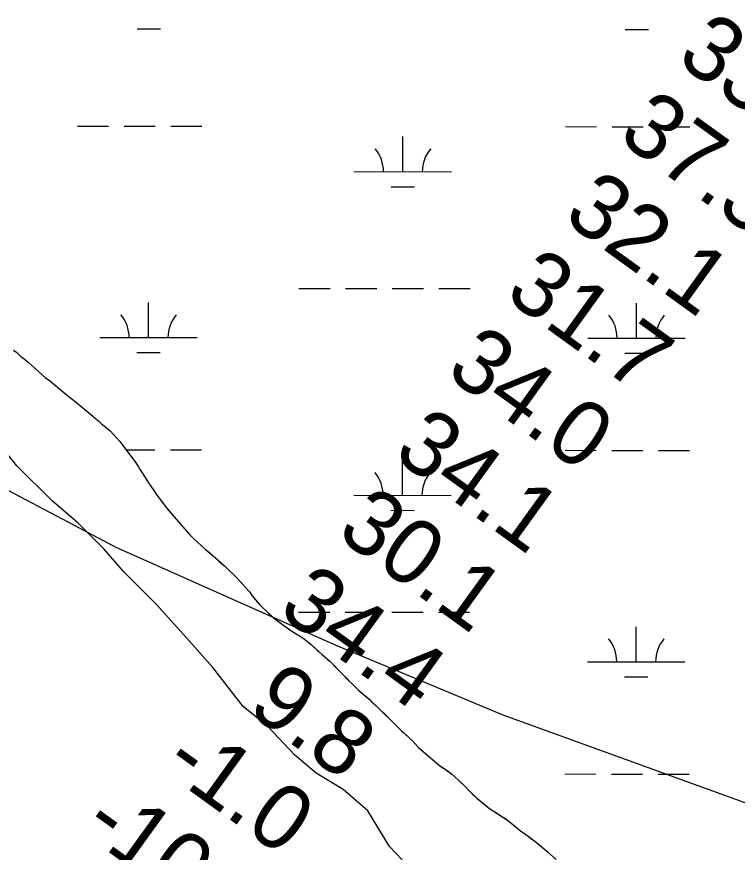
# Model space of a CAD drawing. Extents: x 3148686 to 3186545, y 916144 to 941516.
# Drawn here: x 3160862 to 3161603, y 938344 to 939203 of the extents above; entities that cross this region are included whole.
import ezdxf

# ---------------------------------------------------------------- set-up
doc = ezdxf.new("R2010")
doc.units = 0
for name, color, linetype in [('V-RIVR-EDGE', 7, 'Continuous'), ('V-RIVR-RANG', 7, 'Continuous'), ('V-SITE-VEGE', 7, 'Continuous'), ('V-TOPO-BNDY', 7, 'Continuous'), ('V-WETL-SWMP', 7, 'Continuous')]:
    doc.layers.add(name, color=color, linetype=linetype)

msp = doc.modelspace()

# ---------------------------------------------------------------- linework, layer by layer
at = {"layer": 'V-RIVR-EDGE'}
msp.add_lwpolyline([(3161258.64, 938336.18), (3161245.71, 938349.7), (3161223.5, 938386.58), (3161198.14, 938408.42), (3161170.18, 938425.09), (3161148.44, 938443.81), (3161119.99, 938473.96), (3161095.15, 938493.73), (3161064.13, 938533.74), (3161036.72, 938564.41), (3161005.69, 938598.71), (3160972.58, 938631.99), (3160951.89, 938655.89), (3160924.99, 938682.41), (3160899.11, 938704.77), (3160862.38, 938741.17), (3160806.54, 938811.32)], dxfattribs=at)
at = {"layer": 'V-SITE-VEGE'}
for p, q in [((3160862.24, 938857.39), (3160866.63, 938853.48)), ((3160866.63, 938853.48), (3160870.04, 938851)), ((3160870.04, 938851), (3160874.44, 938847.29)), ((3160874.44, 938847.29), (3160877.43, 938844.41)), ((3160877.43, 938844.41), (3160892.02, 938831.65)), ((3160892.02, 938831.65), (3160895.63, 938828.96)), ((3160895.63, 938828.96), (3160913.03, 938814.53)), ((3160913.03, 938814.53), (3160922.43, 938807.31)), ((3160922.43, 938807.31), (3160934.03, 938797.42)), ((3160934.03, 938797.42), (3160943.04, 938790.2)), ((3160943.04, 938790.2), (3160946.44, 938787.32)), ((3160946.44, 938787.32), (3160949.63, 938784.23)), ((3160949.63, 938784.23), (3160953.83, 938780.93)), ((3160953.83, 938780.93), (3160958.23, 938777.02)), ((3160958.23, 938777.02), (3160961.82, 938773.32)), ((3160961.82, 938773.32), (3160968.19, 938766.15)), ((3160968.19, 938766.15), (3160984.07, 938745.06)), ((3160984.07, 938745.06), (3160987.44, 938740.15)), ((3160987.44, 938740.15), (3160989.22, 938736.89)), ((3160989.22, 938736.89), (3160991.2, 938734.02)), ((3160991.2, 938734.02), (3160998.32, 938722.58)), ((3160998.32, 938722.58), (3161002.69, 938716.64)), ((3161002.69, 938716.64), (3161006.65, 938710.72)), ((3161006.65, 938710.72), (3161016.38, 938697.82)), ((3161016.38, 938697.82), (3161021.75, 938691.26)), ((3161021.75, 938691.26), (3161028.72, 938683.46)), ((3161028.72, 938683.46), (3161032.69, 938678.55)), ((3161032.69, 938678.55), (3161040.26, 938670.14)), ((3161040.26, 938670.14), (3161044.26, 938666.43)), ((3161044.26, 938666.43), (3161047.45, 938663.15)), ((3161047.45, 938663.15), (3161053.04, 938658.21)), ((3161053.04, 938658.21), (3161056.09, 938655.52)), ((3161056.09, 938655.52), (3161064.25, 938648.47)), ((3161064.25, 938648.47), (3161075.96, 938638.13)), ((3161075.96, 938638.13), (3161088.72, 938625.99)), ((3161088.72, 938625.99), (3161092.1, 938622.31)), ((3161092.1, 938622.31), (3161098.23, 938615.35)), ((3161098.23, 938615.35), (3161101.53, 938611.42)), ((3161101.53, 938611.42), (3161104.6, 938607.49)), ((3161104.6, 938607.49), (3161110.24, 938600.62)), ((3161110.24, 938600.62), (3161112.41, 938598.08)), ((3161112.41, 938598.08), (3161115.4, 938595.04)), ((3161115.4, 938595.04), (3161118.38, 938592.26)), ((3161118.38, 938592.26), (3161126.54, 938584.95)), ((3161126.54, 938584.95), (3161129.21, 938582.74)), ((3161129.21, 938582.74), (3161135.52, 938577.97)), ((3161135.52, 938577.97), (3161144.34, 938571.89)), ((3161144.34, 938571.89), (3161150.65, 938567.85)), ((3161150.65, 938567.85), (3161153.89, 938565.96)), ((3161153.89, 938565.96), (3161157.04, 938563.82)), ((3161157.04, 938563.82), (3161161.49, 938560.53)), ((3161161.49, 938560.53), (3161165.37, 938557.16)), ((3161165.37, 938557.16), (3161173.28, 938549.78)), ((3161173.28, 938549.78), (3161176.59, 938546.99)), ((3161176.59, 938546.99), (3161184.27, 938540.1)), ((3161184.27, 938540.1), (3161186.69, 938537.81)), ((3161186.69, 938537.81), (3161195.32, 938529.04)), ((3161195.32, 938529.04), (3161203.79, 938520.11)), ((3161203.79, 938520.11), (3161206.78, 938517.4)), ((3161206.78, 938517.4), (3161213.96, 938510.51)), ((3161213.96, 938510.51), (3161216.47, 938508.22)), ((3161216.47, 938508.22), (3161224.63, 938501.16)), ((3161224.63, 938501.16), (3161236.5, 938490)), ((3161236.5, 938490), (3161245.14, 938481.56)), ((3161245.14, 938481.56), (3161252.24, 938474.35)), ((3161252.24, 938474.35), (3161257.81, 938469.02)), ((3161257.81, 938469.02), (3161269.35, 938458.28)), ((3161269.35, 938458.28), (3161275.97, 938451.23)), ((3161275.97, 938451.23), (3161297.13, 938432.93)), ((3161297.13, 938432.93), (3161303.04, 938429.14)), ((3161303.04, 938429.14), (3161309.67, 938424.29)), ((3161309.67, 938424.29), (3161313.23, 938421.18)), ((3161313.23, 938421.18), (3161316.46, 938418.14)), ((3161316.46, 938418.14), (3161322.75, 938411.99)), ((3161322.75, 938411.99), (3161327.52, 938407.16)), ((3161327.52, 938407.16), (3161335.43, 938399.53)), ((3161335.43, 938399.53), (3161341.24, 938394.77)), ((3161341.24, 938394.77), (3161347.31, 938390.01)), ((3161347.31, 938390.01), (3161350.62, 938387.62)), ((3161350.62, 938387.62), (3161353.94, 938385.4)), ((3161353.94, 938385.4), (3161363.09, 938379.64)), ((3161363.09, 938379.64), (3161368.83, 938375.36)), ((3161368.83, 938375.36), (3161380.39, 938366)), ((3161380.39, 938366), (3161385.8, 938361.98)), ((3161385.8, 938361.98), (3161388.31, 938360.25)), ((3161388.31, 938360.25), (3161396.8, 938353.92)), ((3161396.8, 938353.92), (3161405.21, 938347.11)), ((3161405.21, 938347.11), (3161417.24, 938336.52))]:
    msp.add_line(p, q, dxfattribs=at)
at = {"layer": 'V-TOPO-BNDY'}
msp.add_lwpolyline([(3163062.31, 937127.32), (3163042.08, 937333.1), (3163017.03, 937479.87), (3162982.49, 937628.74), (3162942.16, 937741.6), (3162886.84, 937839.58), (3162771.84, 937963.73), (3162694.07, 938030.53), (3162300.86, 938206.75), (3162175.04, 938243.09), (3161984.61, 938304.69), (3161799.5, 938349.13), (3161614.4, 938393.58), (3161488.55, 938439.11), (3161362.7, 938484.64), (3161190.8, 938556.46), (3160964.51, 938657), (3160729.71, 938780.63), (3160591.89, 938870.33), (3160455.53, 938975.16), (3160435.15, 938990.83), (3160220.3, 939197.87)], dxfattribs=at)
at = {"layer": 'V-WETL-SWMP'}
for p, q in [((3160986.18, 939190.12), (3161010.18, 939190.1)), ((3161488.09, 939189.59), (3161512.09, 939189.57)), ((3160924.67, 939090.19), (3160956.67, 939090.15)), ((3160972.67, 939090.14), (3161004.67, 939090.1)), ((3161020.67, 939090.08), (3161052.67, 939090.05)), ((3161426.58, 939089.66), (3161458.58, 939089.62)), ((3161474.58, 939089.61), (3161506.58, 939089.57)), ((3161522.58, 939089.56), (3161554.58, 939089.52)), ((3161259.47, 939043.4), (3161259.5, 939079.4)), ((3161209.47, 939043.46), (3161309.47, 939043.35)), ((3161247.45, 939027.98), (3161271.45, 939027.96)), ((3161152.5, 938923.44), (3161184.5, 938923.41)), ((3161200.5, 938923.39), (3161232.5, 938923.36)), ((3161248.5, 938923.34), (3161280.5, 938923.31)), ((3161296.5, 938923.29), (3161328.5, 938923.26)), ((3160997.85, 938872.87), (3160997.89, 938908.87)), ((3161499.76, 938872.34), (3161499.8, 938908.34)), ((3160947.85, 938872.92), (3161047.85, 938872.81)), ((3161449.76, 938872.39), (3161549.76, 938872.28)), ((3160859.03, 938859.87), (3160862.24, 938857.39)), ((3160859.03, 938859.87), (3160862.24, 938857.39)), ((3160862.24, 938857.39), (3160866.63, 938853.48)), ((3160862.24, 938857.39), (3160866.63, 938853.48)), ((3160866.63, 938853.48), (3160870.04, 938851)), ((3160866.63, 938853.48), (3160870.04, 938851)), ((3160870.04, 938851), (3160874.44, 938847.29)), ((3160870.04, 938851), (3160874.44, 938847.29)), ((3160985.83, 938857.45), (3161009.83, 938857.42)), ((3161487.74, 938856.92), (3161511.74, 938856.89)), ((3160874.44, 938847.29), (3160877.43, 938844.41)), ((3160874.44, 938847.29), (3160877.43, 938844.41)), ((3160877.43, 938844.41), (3160892.02, 938831.65)), ((3160877.43, 938844.41), (3160892.02, 938831.65)), ((3160892.02, 938831.65), (3160895.63, 938828.96)), ((3160892.02, 938831.65), (3160895.63, 938828.96)), ((3160895.63, 938828.96), (3160913.03, 938814.53)), ((3160895.63, 938828.96), (3160913.03, 938814.53)), ((3160913.03, 938814.53), (3160922.44, 938807.31)), ((3160913.03, 938814.53), (3160922.44, 938807.31)), ((3160922.44, 938807.31), (3160934.03, 938797.42)), ((3160922.44, 938807.31), (3160934.03, 938797.42)), ((3160934.03, 938797.42), (3160943.04, 938790.2)), ((3160934.03, 938797.42), (3160943.04, 938790.2)), ((3160943.04, 938790.2), (3160946.44, 938787.32)), ((3160943.04, 938790.2), (3160946.44, 938787.32)), ((3160946.44, 938787.32), (3160949.63, 938784.24)), ((3160946.44, 938787.32), (3160949.63, 938784.24)), ((3160949.63, 938784.24), (3160953.83, 938780.93)), ((3160949.63, 938784.24), (3160953.83, 938780.93)), ((3160953.83, 938780.93), (3160958.23, 938777.02)), ((3160953.83, 938780.93), (3160958.23, 938777.02)), ((3160958.23, 938777.02), (3160961.82, 938773.33)), ((3160958.23, 938777.02), (3160961.82, 938773.33)), ((3160961.82, 938773.33), (3160968.19, 938766.15)), ((3160961.82, 938773.33), (3160968.19, 938766.15)), ((3160968.19, 938766.15), (3160984.08, 938745.06)), ((3160968.19, 938766.15), (3160984.08, 938745.06)), ((3160974.74, 938757.46), (3161004.32, 938757.43)), ((3161020.32, 938757.41), (3161052.32, 938757.38)), ((3161426.23, 938756.98), (3161458.23, 938756.95)), ((3161474.23, 938756.93), (3161506.23, 938756.9)), ((3161522.23, 938756.88), (3161554.23, 938756.85)), ((3161259.12, 938710.73), (3161259.15, 938746.73)), ((3160984.08, 938745.06), (3160987.44, 938740.15)), ((3160984.08, 938745.06), (3160987.44, 938740.15)), ((3160987.44, 938740.15), (3160989.22, 938736.89)), ((3160987.44, 938740.15), (3160989.22, 938736.89)), ((3160989.22, 938736.89), (3160991.2, 938734.02)), ((3160989.22, 938736.89), (3160991.2, 938734.02)), ((3160991.2, 938734.02), (3160998.32, 938722.58)), ((3160991.2, 938734.02), (3160998.32, 938722.58)), ((3160998.32, 938722.58), (3161002.69, 938716.65)), ((3160998.32, 938722.58), (3161002.69, 938716.65)), ((3161002.69, 938716.65), (3161006.65, 938710.72)), ((3161002.69, 938716.65), (3161006.65, 938710.72)), ((3161006.65, 938710.72), (3161016.38, 938697.82)), ((3161006.65, 938710.72), (3161016.38, 938697.82)), ((3161209.12, 938710.78), (3161309.12, 938710.68)), ((3161016.38, 938697.82), (3161021.75, 938691.26)), ((3161016.38, 938697.82), (3161021.75, 938691.26)), ((3161247.1, 938695.31), (3161271.1, 938695.28)), ((3161021.75, 938691.26), (3161028.72, 938683.47)), ((3161021.75, 938691.26), (3161028.72, 938683.47)), ((3161028.72, 938683.47), (3161032.69, 938678.55)), ((3161028.72, 938683.47), (3161032.69, 938678.55)), ((3161032.69, 938678.55), (3161040.26, 938670.14)), ((3161032.69, 938678.55), (3161040.26, 938670.14)), ((3161040.26, 938670.14), (3161044.26, 938666.43)), ((3161040.26, 938670.14), (3161044.26, 938666.43)), ((3161044.26, 938666.43), (3161047.45, 938663.15)), ((3161044.26, 938666.43), (3161047.45, 938663.15)), ((3161047.45, 938663.15), (3161053.04, 938658.21)), ((3161047.45, 938663.15), (3161053.04, 938658.21)), ((3161053.04, 938658.21), (3161056.09, 938655.53)), ((3161053.04, 938658.21), (3161056.09, 938655.53)), ((3161056.09, 938655.53), (3161059.24, 938652.82)), ((3161056.09, 938655.53), (3161059.24, 938652.82)), ((3161059.24, 938652.82), (3161061.58, 938650.77)), ((3161059.24, 938652.82), (3161061.58, 938650.77)), ((3161061.58, 938650.77), (3161064.25, 938648.47)), ((3161061.58, 938650.77), (3161064.25, 938648.47)), ((3161064.25, 938648.47), (3161066.75, 938646.25)), ((3161064.25, 938648.47), (3161066.75, 938646.25)), ((3161066.75, 938646.25), (3161070.31, 938643.13)), ((3161066.75, 938646.25), (3161070.31, 938643.13)), ((3161070.31, 938643.13), (3161073.05, 938640.67)), ((3161070.31, 938643.13), (3161073.05, 938640.67)), ((3161073.05, 938640.67), (3161075.96, 938638.13)), ((3161073.05, 938640.67), (3161075.96, 938638.13)), ((3161075.96, 938638.13), (3161078.22, 938636)), ((3161075.96, 938638.13), (3161078.22, 938636)), ((3161078.22, 938636), (3161081.29, 938633.13)), ((3161078.22, 938636), (3161081.29, 938633.13)), ((3161081.29, 938633.13), (3161084.04, 938630.42)), ((3161081.29, 938633.13), (3161084.04, 938630.42)), ((3161084.04, 938630.42), (3161086.3, 938628.29)), ((3161084.04, 938630.42), (3161086.3, 938628.29)), ((3161086.3, 938628.29), (3161088.72, 938625.99)), ((3161086.3, 938628.29), (3161088.72, 938625.99)), ((3161088.72, 938625.99), (3161092.11, 938622.31)), ((3161088.72, 938625.99), (3161092.11, 938622.31)), ((3161092.11, 938622.31), (3161094.93, 938619.11)), ((3161092.11, 938622.31), (3161094.93, 938619.11)), ((3161094.93, 938619.11), (3161098.23, 938615.35)), ((3161094.93, 938619.11), (3161098.23, 938615.35)), ((3161098.23, 938615.35), (3161101.54, 938611.42)), ((3161098.23, 938615.35), (3161101.54, 938611.42)), ((3161101.54, 938611.42), (3161104.6, 938607.49)), ((3161101.54, 938611.42), (3161104.6, 938607.49)), ((3161104.6, 938607.49), (3161107.66, 938603.81)), ((3161104.6, 938607.49), (3161107.66, 938603.81)), ((3161107.66, 938603.81), (3161110.24, 938600.62)), ((3161107.66, 938603.81), (3161110.24, 938600.62)), ((3161110.24, 938600.62), (3161112.41, 938598.08)), ((3161110.24, 938600.62), (3161112.41, 938598.08)), ((3161112.41, 938598.08), (3161115.4, 938595.05)), ((3161112.41, 938598.08), (3161115.4, 938595.05)), ((3161115.4, 938595.05), (3161118.39, 938592.26)), ((3161115.4, 938595.05), (3161118.39, 938592.26)), ((3161118.39, 938592.26), (3161120.89, 938590.04)), ((3161118.39, 938592.26), (3161120.89, 938590.04)), ((3161120.89, 938590.04), (3161123.64, 938587.58)), ((3161120.89, 938590.04), (3161123.64, 938587.58)), ((3161123.64, 938587.58), (3161126.54, 938584.96)), ((3161123.64, 938587.58), (3161126.54, 938584.96)), ((3161126.54, 938584.96), (3161129.21, 938582.74)), ((3161126.54, 938584.96), (3161129.21, 938582.74)), ((3161129.21, 938582.74), (3161132.53, 938580.19)), ((3161129.21, 938582.74), (3161132.53, 938580.19)), ((3161152.15, 938590.77), (3161184.15, 938590.74)), ((3161200.15, 938590.72), (3161232.15, 938590.69)), ((3161248.15, 938590.67), (3161280.15, 938590.64)), ((3161296.15, 938590.62), (3161328.14, 938590.58)), ((3161132.53, 938580.19), (3161135.52, 938577.97)), ((3161132.53, 938580.19), (3161135.52, 938577.97)), ((3161135.52, 938577.97), (3161138.11, 938576.16)), ((3161135.52, 938577.97), (3161138.11, 938576.16)), ((3161138.11, 938576.16), (3161141.5, 938573.78)), ((3161138.11, 938576.16), (3161141.5, 938573.78)), ((3161499.41, 938539.66), (3161499.45, 938575.66)), ((3161141.5, 938573.78), (3161144.34, 938571.89)), ((3161141.5, 938573.78), (3161144.34, 938571.89)), ((3161144.34, 938571.89), (3161147.57, 938569.83)), ((3161144.34, 938571.89), (3161147.57, 938569.83)), ((3161147.57, 938569.83), (3161150.65, 938567.85)), ((3161147.57, 938569.83), (3161150.65, 938567.85)), ((3161150.65, 938567.85), (3161153.89, 938565.96)), ((3161150.65, 938567.85), (3161153.89, 938565.96)), ((3161153.89, 938565.96), (3161157.04, 938563.82)), ((3161153.89, 938565.96), (3161157.04, 938563.82)), ((3161157.04, 938563.82), (3161161.49, 938560.53)), ((3161157.04, 938563.82), (3161161.49, 938560.53)), ((3161161.49, 938560.53), (3161165.37, 938557.17)), ((3161161.49, 938560.53), (3161165.37, 938557.17)), ((3161165.37, 938557.17), (3161167.95, 938554.71)), ((3161165.37, 938557.17), (3161167.95, 938554.71)), ((3161167.95, 938554.71), (3161170.86, 938552)), ((3161167.95, 938554.71), (3161170.86, 938552)), ((3161170.86, 938552), (3161173.28, 938549.78)), ((3161170.86, 938552), (3161173.28, 938549.78)), ((3161173.28, 938549.78), (3161176.59, 938546.99)), ((3161173.28, 938549.78), (3161176.59, 938546.99)), ((3161176.59, 938546.99), (3161179.18, 938544.7)), ((3161176.59, 938546.99), (3161179.18, 938544.7)), ((3161179.18, 938544.7), (3161182, 938542.15)), ((3161179.18, 938544.7), (3161182, 938542.15)), ((3161182, 938542.15), (3161184.27, 938540.1)), ((3161182, 938542.15), (3161184.27, 938540.1)), ((3161184.27, 938540.1), (3161186.69, 938537.81)), ((3161184.27, 938540.1), (3161186.69, 938537.81)), ((3161186.69, 938537.81), (3161189.59, 938534.86)), ((3161186.69, 938537.81), (3161189.59, 938534.86)), ((3161189.59, 938534.86), (3161192.5, 938531.82)), ((3161189.59, 938534.86), (3161192.5, 938531.82)), ((3161192.5, 938531.82), (3161195.32, 938529.04)), ((3161192.5, 938531.82), (3161195.32, 938529.04)), ((3161449.41, 938539.71), (3161549.41, 938539.61)), ((3161195.32, 938529.04), (3161197.98, 938526.17)), ((3161195.32, 938529.04), (3161197.98, 938526.17)), ((3161197.98, 938526.17), (3161201.37, 938522.65)), ((3161197.98, 938526.17), (3161201.37, 938522.65)), ((3161201.37, 938522.65), (3161203.79, 938520.11)), ((3161201.37, 938522.65), (3161203.79, 938520.11)), ((3161487.39, 938524.24), (3161511.39, 938524.22)), ((3161203.79, 938520.11), (3161206.78, 938517.4)), ((3161203.79, 938520.11), (3161206.78, 938517.4)), ((3161206.78, 938517.4), (3161209.36, 938514.86)), ((3161206.78, 938517.4), (3161209.36, 938514.86)), ((3161209.36, 938514.86), (3161211.71, 938512.64)), ((3161209.36, 938514.86), (3161211.71, 938512.64)), ((3161211.71, 938512.64), (3161213.97, 938510.51)), ((3161211.71, 938512.64), (3161213.97, 938510.51)), ((3161213.97, 938510.51), (3161216.47, 938508.22)), ((3161213.97, 938510.51), (3161216.47, 938508.22)), ((3161216.47, 938508.22), (3161218.97, 938506.08)), ((3161216.47, 938508.22), (3161218.97, 938506.08)), ((3161218.97, 938506.08), (3161221.56, 938503.87)), ((3161218.97, 938506.08), (3161221.56, 938503.87)), ((3161221.56, 938503.87), (3161224.63, 938501.16)), ((3161221.56, 938503.87), (3161224.63, 938501.16)), ((3161224.63, 938501.16), (3161227.29, 938498.62)), ((3161224.63, 938501.16), (3161227.29, 938498.62)), ((3161227.29, 938498.62), (3161230.68, 938495.42)), ((3161227.29, 938498.62), (3161230.68, 938495.42)), ((3161230.68, 938495.42), (3161233.67, 938492.63)), ((3161230.68, 938495.42), (3161233.67, 938492.63)), ((3161233.67, 938492.63), (3161236.5, 938490.01)), ((3161233.67, 938492.63), (3161236.5, 938490.01)), ((3161236.5, 938490.01), (3161239.73, 938486.89)), ((3161236.5, 938490.01), (3161239.73, 938486.89)), ((3161239.73, 938486.89), (3161242.07, 938484.51)), ((3161239.73, 938486.89), (3161242.07, 938484.51)), ((3161242.07, 938484.51), (3161245.14, 938481.56)), ((3161242.07, 938484.51), (3161245.14, 938481.56)), ((3161245.14, 938481.56), (3161247.31, 938479.27)), ((3161245.14, 938481.56), (3161247.31, 938479.27)), ((3161247.31, 938479.27), (3161249.81, 938476.73)), ((3161247.31, 938479.27), (3161249.81, 938476.73)), ((3161249.81, 938476.73), (3161252.24, 938474.35)), ((3161249.81, 938476.73), (3161252.24, 938474.35)), ((3161252.24, 938474.35), (3161255.3, 938471.4)), ((3161252.24, 938474.35), (3161255.3, 938471.4)), ((3161255.3, 938471.4), (3161257.81, 938469.02)), ((3161255.3, 938471.4), (3161257.81, 938469.02)), ((3161257.81, 938469.02), (3161260.55, 938466.48)), ((3161257.81, 938469.02), (3161260.55, 938466.48)), ((3161260.55, 938466.48), (3161263.46, 938463.77)), ((3161260.55, 938466.48), (3161263.46, 938463.77)), ((3161263.46, 938463.77), (3161266.2, 938461.23)), ((3161263.46, 938463.77), (3161266.2, 938461.23)), ((3161266.2, 938461.23), (3161269.35, 938458.28)), ((3161266.2, 938461.23), (3161269.35, 938458.28)), ((3161269.35, 938458.28), (3161272.74, 938454.67)), ((3161269.35, 938458.28), (3161272.74, 938454.67)), ((3161272.74, 938454.67), (3161275.97, 938451.23)), ((3161272.74, 938454.67), (3161275.97, 938451.23)), ((3161275.97, 938451.23), (3161297.13, 938432.93)), ((3161275.97, 938451.23), (3161297.13, 938432.93)), ((3161297.13, 938432.93), (3161299.64, 938431.29)), ((3161297.13, 938432.93), (3161299.64, 938431.29)), ((3161299.64, 938431.29), (3161303.04, 938429.14)), ((3161299.64, 938431.29), (3161303.04, 938429.14)), ((3161303.04, 938429.14), (3161306.36, 938426.76)), ((3161303.04, 938429.14), (3161306.36, 938426.76)), ((3161306.36, 938426.76), (3161309.67, 938424.29)), ((3161306.36, 938426.76), (3161309.67, 938424.29)), ((3161309.67, 938424.29), (3161313.23, 938421.18)), ((3161309.67, 938424.29), (3161313.23, 938421.18)), ((3161313.23, 938421.18), (3161316.46, 938418.14)), ((3161313.23, 938421.18), (3161316.46, 938418.14)), ((3161425.88, 938424.31), (3161457.88, 938424.27)), ((3161473.88, 938424.26), (3161505.88, 938424.22)), ((3161521.88, 938424.21), (3161553.88, 938424.17)), ((3161316.46, 938418.14), (3161319.2, 938415.44)), ((3161316.46, 938418.14), (3161319.2, 938415.44)), ((3161319.2, 938415.44), (3161322.75, 938411.99)), ((3161319.2, 938415.44), (3161322.75, 938411.99)), ((3161322.75, 938411.99), (3161327.52, 938407.16)), ((3161322.75, 938411.99), (3161327.52, 938407.16)), ((3161327.52, 938407.16), (3161330.74, 938404.04)), ((3161327.52, 938407.16), (3161330.74, 938404.04)), ((3161330.74, 938404.04), (3161333.17, 938401.75)), ((3161330.74, 938404.04), (3161333.17, 938401.75)), ((3161333.17, 938401.75), (3161335.43, 938399.53)), ((3161333.17, 938401.75), (3161335.43, 938399.53)), ((3161335.43, 938399.53), (3161338.66, 938396.91)), ((3161335.43, 938399.53), (3161338.66, 938396.91)), ((3161338.66, 938396.91), (3161341.25, 938394.77)), ((3161338.66, 938396.91), (3161341.25, 938394.77)), ((3161341.25, 938394.77), (3161344.16, 938392.47)), ((3161341.25, 938394.77), (3161344.16, 938392.47)), ((3161344.16, 938392.47), (3161347.31, 938390.01)), ((3161344.16, 938392.47), (3161347.31, 938390.01)), ((3161347.31, 938390.01), (3161350.62, 938387.62)), ((3161347.31, 938390.01), (3161350.62, 938387.62)), ((3161350.62, 938387.62), (3161353.94, 938385.4)), ((3161350.62, 938387.62), (3161353.94, 938385.4)), ((3161353.94, 938385.4), (3161356.53, 938383.84)), ((3161353.94, 938385.4), (3161356.53, 938383.84)), ((3161356.53, 938383.84), (3161360.34, 938381.37)), ((3161356.53, 938383.84), (3161360.34, 938381.37)), ((3161360.34, 938381.37), (3161363.09, 938379.64)), ((3161360.34, 938381.37), (3161363.09, 938379.64)), ((3161363.09, 938379.64), (3161365.68, 938377.75)), ((3161363.09, 938379.64), (3161365.68, 938377.75)), ((3161365.68, 938377.75), (3161368.83, 938375.36)), ((3161365.68, 938377.75), (3161368.83, 938375.36)), ((3161368.83, 938375.36), (3161372.38, 938372.49)), ((3161368.83, 938375.36), (3161372.38, 938372.49)), ((3161372.38, 938372.49), (3161374.89, 938370.44)), ((3161372.38, 938372.49), (3161374.89, 938370.44)), ((3161374.89, 938370.44), (3161377.88, 938367.97)), ((3161374.89, 938370.44), (3161377.88, 938367.97)), ((3161377.88, 938367.97), (3161380.39, 938366)), ((3161377.88, 938367.97), (3161380.39, 938366)), ((3161380.39, 938366), (3161382.81, 938364.2)), ((3161380.39, 938366), (3161382.81, 938364.2)), ((3161382.81, 938364.2), (3161385.8, 938361.98)), ((3161382.81, 938364.2), (3161385.8, 938361.98)), ((3161385.8, 938361.98), (3161388.31, 938360.25)), ((3161385.8, 938361.98), (3161388.31, 938360.25)), ((3161388.31, 938360.25), (3161391.22, 938358.03)), ((3161388.31, 938360.25), (3161391.22, 938358.03)), ((3161391.22, 938358.03), (3161393.73, 938356.22)), ((3161391.22, 938358.03), (3161393.73, 938356.22)), ((3161393.73, 938356.22), (3161396.8, 938353.92)), ((3161393.73, 938356.22), (3161396.8, 938353.92)), ((3161396.8, 938353.92), (3161399.39, 938351.87)), ((3161396.8, 938353.92), (3161399.39, 938351.87)), ((3161399.39, 938351.87), (3161405.21, 938347.11)), ((3161399.39, 938351.87), (3161405.21, 938347.11)), ((3161405.21, 938347.11), (3161409.01, 938343.82)), ((3161405.21, 938347.11), (3161409.01, 938343.82))]:
    msp.add_line(p, q, dxfattribs=at)
for centre, start, end in [((3161204.22, 939043.94), 359.16781, 40.71147), ((3161314.71, 939043.82), 139.1678, 180.71146), ((3160942.61, 938873.4), 359.16781, 40.71147), ((3161053.09, 938873.28), 139.1678, 180.71146), ((3161444.52, 938872.87), 359.16781, 40.71147), ((3161555, 938872.75), 139.1678, 180.71146), ((3161203.87, 938711.26), 359.16781, 40.71147), ((3161314.36, 938711.14), 139.1678, 180.71146), ((3161444.17, 938540.2), 359.16781, 40.71147), ((3161554.65, 938540.08), 139.1678, 180.71146)]:
    msp.add_arc(centre, 35.25, start, end, dxfattribs=at)

# ---------------------------------------------------------------- texts
at = {"layer": 'V-RIVR-RANG'}
for s, p in [('33.1', (3161539.19, 939156.96)), ('37.3', (3161478.98, 939077.09)), ('32.1', (3161422.62, 938994.45)), ('31.7', (3161362.41, 938914.58)), ('34.0', (3161301.77, 938835.02)), ('34.1', (3161247.76, 938750.68)), ('30.1', (3161189.47, 938669.42)), ('34.4', (3161129.26, 938589.55)), ('9.8', (3161097.93, 938488.86)), ('-1.0', (3161010.33, 938428.74)), ('-10.8', (3160927.44, 938365.22))]:
    msp.add_text(s, height=67, rotation=324.20833, dxfattribs=at).set_placement(p)

doc.saveas('drawing.dxf')
